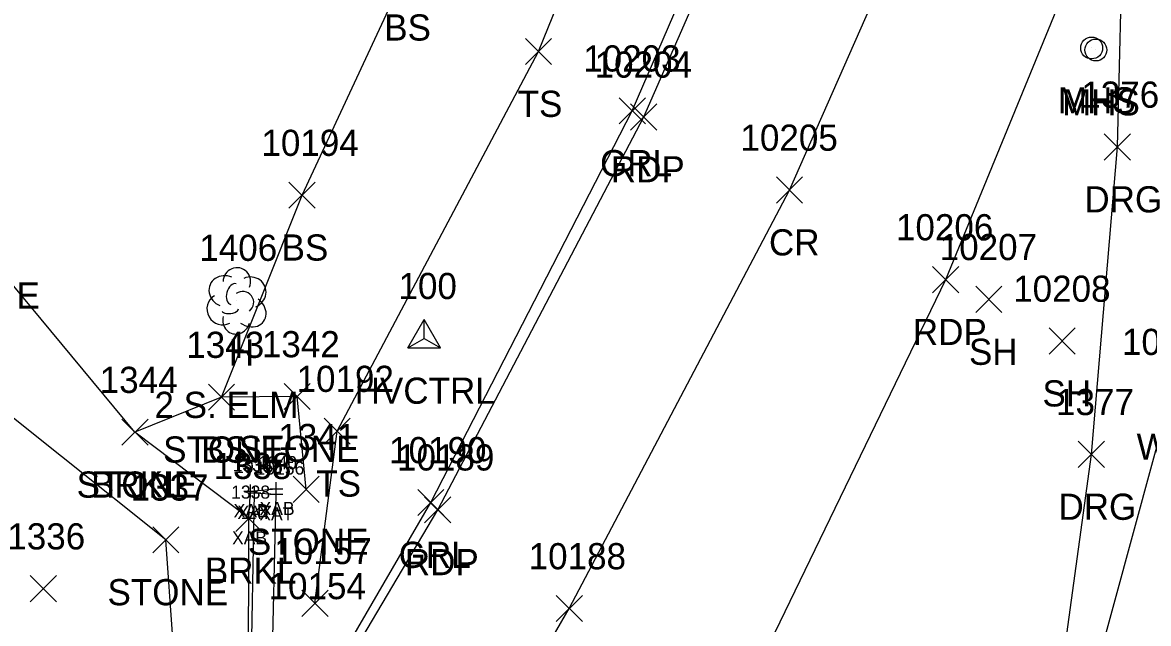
# Model space of a CAD drawing. Extents: x 1651685 to 1653558, y 889533 to 891085.
# Drawn here: x 1652681.1 to 1652767.1, y 890291.8 to 890337.8 of the extents above; entities that cross this region are included whole.
import ezdxf

# ---------------------------------------------------------------- set-up
doc = ezdxf.new("R2010")
doc.units = 0
for name, color, linetype in [('B_A', 7, 'Continuous'), ('B_I', 7, 'Continuous'), ('B_TIC', 7, 'Continuous'), ('BSUBM', 7, 'Continuous'), ('C_A', 7, 'Continuous'), ('C_I', 7, 'Continuous'), ('CPSM', 7, 'Continuous'), ('L_A', 7, 'Continuous'), ('L_C', 7, 'Continuous'), ('L_I', 7, 'Continuous'), ('L_TIC', 7, 'Continuous'), ('LASF', 7, 'Continuous'), ('LAWA', 7, 'Continuous'), ('LAWE', 7, 'Continuous'), ('LELB', 7, 'Continuous'), ('LTD', 7, 'Continuous'), ('P_A', 7, 'Continuous'), ('P_I', 7, 'Continuous'), ('P_TIC', 7, 'Continuous'), ('PET', 7, 'Continuous'), ('PRC', 7, 'Continuous'), ('R_A', 7, 'Continuous'), ('R_I', 7, 'Continuous'), ('R_TIC', 7, 'Continuous'), ('RDG', 7, 'Continuous'), ('RGR', 7, 'Continuous'), ('U_A', 7, 'Continuous'), ('U_I', 7, 'Continuous'), ('USMH', 7, 'Continuous')]:
    doc.layers.add(name, color=color, linetype=linetype)

msp = doc.modelspace()

# ---------------------------------------------------------------- linework, layer by layer
at = {"layer": 'B_TIC'}
for p, q in [((1652700.489, 890302.125), (1652700.564, 890302.125)), ((1652698.508, 890301.956), (1652698.583, 890301.956)), ((1652698.818, 890301.832), (1652698.894, 890301.832)), ((1652700.487, 890301.714), (1652700.562, 890301.714)), ((1652700.487, 890301.714), (1652700.562, 890301.714)), ((1652698.388, 890299.877), (1652698.464, 890299.877))]:
    msp.add_line(p, q, dxfattribs=at)
for points in [[(1652698.504, 890301.456), (1652698.504, 890302.456)], [(1652698.815, 890301.332), (1652698.815, 890302.332)], [(1652699.985, 890302.125), (1652700.985, 890302.125)], [(1652700.483, 890301.214), (1652700.483, 890302.214)], [(1652700.483, 890301.214), (1652700.483, 890302.214)], [(1652700.485, 890301.625), (1652700.485, 890302.625)], [(1652698.004, 890301.956), (1652699.004, 890301.956)], [(1652698.315, 890301.832), (1652699.315, 890301.832)], [(1652699.983, 890301.714), (1652700.983, 890301.714)], [(1652699.983, 890301.714), (1652700.983, 890301.714)], [(1652698.385, 890299.377), (1652698.385, 890300.377)], [(1652697.885, 890299.877), (1652698.885, 890299.877)]]:
    msp.add_lwpolyline(points, dxfattribs=at)
at = {"layer": 'BSUBM'}
for points in [[(1652730.91, 890251.239), (1652729.609, 890250.415), (1652721.751, 890259.535), (1652713.874, 890268.743), (1652713.817, 890268.822), (1652702.155, 890282.607), (1652701.912, 890282.515), (1652698.364, 890286.414), (1652698.385, 890299.877), (1652698.504, 890301.956), (1652700.485, 890302.125)], [(1652700.137, 890287.511), (1652700.966, 890286.566), (1652700.029, 890285.003), (1652698.538, 890286.578), (1652698.815, 890301.832), (1652700.483, 890301.714)], [(1652700.137, 890287.511), (1652700.483, 890301.714)]]:
    msp.add_lwpolyline(points, dxfattribs=at)
at = {"layer": 'CPSM'}
for p, q in [((1652710.529, 890312.904), (1652711.779, 890315.069)), ((1652713.029, 890312.904), (1652711.779, 890315.069)), ((1652711.78, 890313.626), (1652711.779, 890315.069)), ((1652710.529, 890312.904), (1652711.78, 890313.626)), ((1652711.78, 890313.626), (1652711.78, 890313.626)), ((1652711.78, 890313.626), (1652713.029, 890312.904)), ((1652710.529, 890312.904), (1652713.029, 890312.904))]:
    msp.add_line(p, q, dxfattribs=at)
at = {"layer": 'L_TIC'}
for points in [[(1652719.509, 890334.546), (1652721.509, 890336.546)], [(1652721.509, 890334.546), (1652719.509, 890336.546)], [(1652701.45, 890323.566), (1652703.45, 890325.566)], [(1652703.45, 890323.566), (1652701.45, 890325.566)], [(1652701.45, 890323.566), (1652703.45, 890325.566)], [(1652703.45, 890323.566), (1652701.45, 890325.566)], [(1652753.907, 890315.601), (1652755.907, 890317.601)], [(1652755.907, 890315.601), (1652753.907, 890317.601)], [(1652759.519, 890312.42), (1652761.519, 890314.42)], [(1652761.519, 890312.42), (1652759.519, 890314.42)], [(1652695.302, 890308.132), (1652697.302, 890310.132)], [(1652697.302, 890308.132), (1652695.302, 890310.132)], [(1652695.302, 890308.132), (1652697.302, 890310.132)], [(1652697.302, 890308.132), (1652695.302, 890310.132)], [(1652701.077, 890308.179), (1652703.077, 890310.179)], [(1652703.077, 890308.179), (1652701.077, 890310.179)], [(1652688.689, 890305.453), (1652690.689, 890307.453)], [(1652690.689, 890305.453), (1652688.689, 890307.453)], [(1652688.689, 890305.453), (1652690.689, 890307.453)], [(1652690.689, 890305.453), (1652688.689, 890307.453)], [(1652704.136, 890305.532), (1652706.136, 890307.532)], [(1652706.136, 890305.532), (1652704.136, 890307.532)], [(1652701.771, 890301.086), (1652703.771, 890303.086)], [(1652703.771, 890301.086), (1652701.771, 890303.086)], [(1652697.385, 890298.877), (1652699.385, 890300.877)], [(1652699.385, 890298.877), (1652697.385, 890300.877)], [(1652691.048, 890297.23), (1652693.048, 890299.23)], [(1652693.048, 890297.23), (1652691.048, 890299.23)], [(1652681.687, 890293.495), (1652683.687, 890295.495)], [(1652683.687, 890293.495), (1652681.687, 890295.495)], [(1652702.441, 890292.375), (1652704.441, 890294.375)], [(1652704.441, 890292.375), (1652702.441, 890294.375)]]:
    msp.add_lwpolyline(points, dxfattribs=at)
at = {"layer": 'LASF'}
for points in [[(1652702.399, 890272.508), (1652693.116, 890283.145), (1652692.048, 890298.23), (1652676.075, 890310.97), (1652670.462, 890321.805), (1652673.396, 890326.853)], [(1652702.771, 890302.086), (1652702.077, 890309.179), (1652696.302, 890309.132), (1652689.689, 890306.453), (1652677.675, 890320.897), (1652673.396, 890326.853)]]:
    msp.add_lwpolyline(points, dxfattribs=at)
at = {"layer": 'LAWA'}
msp.add_lwpolyline([(1652733.239, 890255.045), (1652739.873, 890255.528), (1652757.329, 890267.071), (1652768.835, 890309.355), (1652781.068, 890350.147), (1652797.707, 890393.693), (1652815.714, 890436.04), (1652825.054, 890456.619), (1652833.352, 890477.684), (1652833.388, 890492.3)], dxfattribs=at)
at = {"layer": 'LAWE'}
msp.add_lwpolyline([(1652698.385, 890299.877), (1652689.689, 890306.453)], dxfattribs=at)
at = {"layer": 'LELB'}
for points in [[(1652703.441, 890293.375), (1652705.136, 890306.532), (1652720.509, 890335.546), (1652734.79, 890370.785), (1652740.485, 890380.177), (1652745.045, 890383.574), (1652748.855, 890403.842), (1652752.072, 890412.251), (1652759.38, 890425.618), (1652765.142, 890443.503), (1652773.03, 890464.558), (1652787.9, 890509.347)], [(1652702.45, 890324.566), (1652710.288, 890341.379), (1652723.874, 890374.581)], [(1652696.302, 890309.132), (1652702.45, 890324.566)]]:
    msp.add_lwpolyline(points, dxfattribs=at)
at = {"layer": 'LTD'}
msp.add_line((1652697.43, 890316.544), (1652697.43, 890316.544), dxfattribs=at)
msp.add_line((1652697.43, 890316.544), (1652697.43, 890316.544), dxfattribs=at)
msp.add_arc((1652697.477, 890317.978), 1.047, 335.52715, 180.95627, dxfattribs=at)
for centre, major_axis, ratio, start_param, end_param in [((1652696.638, 890317.211), (1.21, -0.512), 0.895232, 1.570796, 4.712389), ((1652698.471, 890317.128), (-1.141, -0.483), 0.949671, 1.570796, 4.712389), ((1652697.221, 890317.002), (-0.208, -0.792), 0.645439, 3.141593, 6.283185), ((1652696.347, 890315.836), (0.584, -1.042), 0.959034, 3.141593, 6.283185), ((1652697.93, 890316.377), (-0.5, 0.667), 0.989748, 3.141593, 6.283185), ((1652698.43, 890315.711), (-1.09, 0.792), 0.841452, 1.570796, 4.712389), ((1652696.972, 890315.794), (-0.625, -0.083), 0.423636, 0, 3.141593), ((1652697.43, 890315.044), (0.265, 1.061), 0.942809, 1.570796, 4.712389)]:
    msp.add_ellipse(centre, major_axis=major_axis, ratio=ratio, start_param=start_param, end_param=end_param, dxfattribs=at)
at = {"layer": 'P_TIC'}
for points in [[(1652727.548, 890329.545), (1652729.548, 890331.545)], [(1652729.548, 890329.545), (1652727.548, 890331.545)], [(1652738.686, 890323.96), (1652740.686, 890325.96)], [(1652740.686, 890323.96), (1652738.686, 890325.96)], [(1652750.621, 890317.115), (1652752.621, 890319.115)], [(1652752.621, 890317.115), (1652750.621, 890319.115)], [(1652711.816, 890299.527), (1652713.816, 890301.527)], [(1652713.816, 890299.527), (1652711.816, 890301.527)], [(1652721.864, 890291.979), (1652723.864, 890293.979)], [(1652723.864, 890291.979), (1652721.864, 890293.979)]]:
    msp.add_lwpolyline(points, dxfattribs=at)
at = {"layer": 'PET'}
for points in [[(1652703.162, 890284.218), (1652712.816, 890300.527), (1652728.548, 890330.545), (1652742.129, 890361.562), (1652749.201, 890378.01), (1652759.762, 890406.833), (1652771.728, 890443.525), (1652776.682, 890458.628), (1652791.905, 890507.528)], [(1652703.162, 890284.218), (1652712.038, 890274.257), (1652722.331, 890261.916), (1652735.137, 890284.012), (1652751.621, 890318.115), (1652767.723, 890357.351), (1652783.179, 890400.145), (1652797.7, 890444.761), (1652815.977, 890499.358)]]:
    msp.add_lwpolyline(points, dxfattribs=at)
at = {"layer": 'PRC'}
msp.add_lwpolyline([(1652712.038, 890274.257), (1652722.864, 890292.979), (1652739.686, 890324.96), (1652756.287, 890362.602), (1652772.674, 890406.812), (1652786.214, 890448.938), (1652804.537, 890503.78)], dxfattribs=at)
at = {"layer": 'R_TIC'}
for points in [[(1652726.675, 890330.014), (1652728.675, 890332.014)], [(1652728.675, 890330.014), (1652726.675, 890332.014)], [(1652763.722, 890327.25), (1652765.722, 890329.25)], [(1652765.722, 890327.25), (1652763.722, 890329.25)], [(1652761.74, 890303.759), (1652763.74, 890305.759)], [(1652763.74, 890303.759), (1652761.74, 890305.759)], [(1652711.293, 890300.085), (1652713.293, 890302.085)], [(1652713.293, 890300.085), (1652711.293, 890302.085)]]:
    msp.add_lwpolyline(points, dxfattribs=at)
at = {"layer": 'RDG'}
msp.add_lwpolyline([(1652765.146, 890345.746), (1652764.722, 890328.25), (1652762.74, 890304.759), (1652758.96, 890277.3), (1652744.884, 890274.965), (1652728.277, 890271.77)], dxfattribs=at)
at = {"layer": 'RGR'}
msp.add_lwpolyline([(1652703.785, 890286.446), (1652712.293, 890301.085), (1652727.675, 890331.014), (1652743.089, 890366.713), (1652744.455, 890374.508), (1652743.705, 890381.112)], dxfattribs=at)
at = {"layer": 'USMH'}
for p, q in [((1652762.767, 890335.813), (1652762.767, 890335.813)), ((1652763.09, 890335.66), (1652763.09, 890335.66)), ((1652763.601, 890335.813), (1652763.601, 890335.813)), ((1652763.923, 890335.66), (1652763.923, 890335.66))]:
    msp.add_line(p, q, dxfattribs=at)
for centre in [(1652762.767, 890335.813), (1652763.09, 890335.66)]:
    msp.add_circle(centre, 0.833, dxfattribs=at)

# ---------------------------------------------------------------- texts
at = {"layer": 'B_A'}
for s, p in [('XAB', (1652699.206, 890300.125)), ('XAB', (1652697.225, 890299.956)), ('XAT', (1652697.52, 890299.832)), ('XAT', (1652699.188, 890299.714)), ('XAT', (1652699.188, 890299.714)), ('XAB', (1652697.105, 890297.877))]:
    msp.add_text(s, height=1, dxfattribs=at).set_placement(p)
at = {"layer": 'B_I'}
for s, p in [('1340', (1652699.096, 890303.625)), ('1339', (1652697.154, 890303.456)), ('10155', (1652697.264, 890303.332)), ('10156', (1652698.905, 890303.214)), ('10156', (1652698.905, 890303.214)), ('1338', (1652697.038, 890301.377))]:
    msp.add_text(s, height=1, dxfattribs=at).set_placement(p)
at = {"layer": 'C_A'}
msp.add_text('HVCTRL', height=2, dxfattribs=at).set_placement((1652706.473, 890308.626))
at = {"layer": 'C_I'}
msp.add_text('100', height=2, dxfattribs=at).set_placement((1652709.819, 890316.626))
at = {"layer": 'L_A'}
for s, p in [('BS', (1652708.729, 890336.379)), ('TS', (1652718.918, 890330.546)), ('BS', (1652700.891, 890319.566)), ('BS', (1652700.891, 890319.566)), ('STONE', (1652673.218, 890315.897)), ('H', (1652696.863, 890311.544)), ('SH', (1652753.395, 890311.601)), ('SH', (1652759.007, 890308.42)), ('WDR', (1652766.197, 890304.355)), ('STONE', (1652691.845, 890304.132)), ('BS', (1652694.743, 890304.132)), ('STONE', (1652697.62, 890304.179)), ('STONE', (1652685.232, 890301.453)), ('BRKL', (1652686.334, 890301.453)), ('TS', (1652703.546, 890301.532)), ('STONE', (1652698.315, 890297.086)), ('BRKL', (1652695.03, 890294.877)), ('STONE', (1652687.592, 890293.23))]:
    msp.add_text(s, height=2, dxfattribs=at).set_placement(p)
at = {"layer": 'L_C'}
msp.add_text('2 S. ELM', height=2, dxfattribs=at).set_placement((1652691.178, 890307.544))
at = {"layer": 'L_I'}
for s, p in [('10194', (1652699.348, 890327.566)), ('10194', (1652699.348, 890327.566)), ('1406', (1652694.603, 890319.544)), ('10207', (1652751.159, 890319.601)), ('10208', (1652756.771, 890316.42)), ('1343', (1652693.609, 890312.132)), ('1343', (1652693.609, 890312.132)), ('1342', (1652699.384, 890312.179)), ('10209', (1652765.079, 890312.355)), ('10209', (1652765.079, 890312.355)), ('1344', (1652686.996, 890309.453)), ('1344', (1652686.996, 890309.453)), ('10192', (1652702.034, 890309.532)), ('1341', (1652700.646, 890305.086)), ('1338', (1652695.692, 890302.877)), ('1337', (1652689.356, 890301.23)), ('1336', (1652679.939, 890297.495)), ('10157', (1652700.339, 890296.375))]:
    msp.add_text(s, height=2, dxfattribs=at).set_placement(p)
at = {"layer": 'P_A'}
for s, p in [('RDP', (1652726.036, 890325.545)), ('CR', (1652738.119, 890319.96)), ('RDP', (1652749.109, 890313.115)), ('RDP', (1652710.304, 890295.527))]:
    msp.add_text(s, height=2, dxfattribs=at).set_placement(p)
at = {"layer": 'P_I'}
for s, p in [('10204', (1652724.8, 890333.545)), ('10205', (1652735.938, 890327.96)), ('10206', (1652747.818, 890321.115)), ('10189', (1652709.706, 890303.527)), ('10188', (1652719.762, 890295.979))]:
    msp.add_text(s, height=2, dxfattribs=at).set_placement(p)
at = {"layer": 'R_A'}
for s, p in [('GRL', (1652725.218, 890326.014)), ('DRG', (1652762.21, 890323.25)), ('DRG', (1652760.228, 890299.759)), ('GRL', (1652709.836, 890296.085))]:
    msp.add_text(s, height=2, dxfattribs=at).set_placement(p)
at = {"layer": 'R_I'}
for s, p in [('10203', (1652723.927, 890334.014)), ('1376', (1652761.974, 890331.25)), ('1377', (1652760.047, 890307.759)), ('10190', (1652709.104, 890304.085))]:
    msp.add_text(s, height=2, dxfattribs=at).set_placement(p)
at = {"layer": 'U_A'}
for p in [(1652760.185, 890330.813), (1652760.507, 890330.66)]:
    msp.add_text('MHS', height=2, dxfattribs=at).set_placement(p)
at = {"layer": 'U_I'}
msp.add_text('10154', height=2, dxfattribs=at).set_placement((1652699.893, 890293.696))

doc.saveas('drawing.dxf')
